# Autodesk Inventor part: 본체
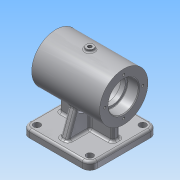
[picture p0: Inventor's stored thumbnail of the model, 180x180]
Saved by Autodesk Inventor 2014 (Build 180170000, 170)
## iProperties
Created: 2019-06
Part Number: 본체
Material: 알루미늄 6061
Document SubType Name: Modeling
Designer: user
Density: 2.71 g/cm^3
Appearance: 알루미늄 - 평지
Mass: 688.176 g
Surface Area: 608.027 cm^2
Volume: 253.94 cm^3
Author: user
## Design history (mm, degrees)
sketch "스케치1"
  geometry: L1 (-45, 0)-(45, 0); L2 (-45, 0)-(-45, 32); L3 (-45, 32)-(45, 32); L4 (45, 32)-(45, 0); L5 (-45, 20)-(-30, 20); L6 (-30, 20)-(-30, 17); L7 (-30, 17)-(-24, 17); L8 (-24, 17)-(-24, 25); L9 (-24, 25)-(24, 25); L10 (24, 25)-(24, 17); L11 (24, 17)-(30, 17); L12 (30, 17)-(30, 20); L13 (30, 20)-(45, 20); 2 further points
  constraints: 26 end point, 7 parallel, 4 perpendicular, 2 point on line, 1 coincident, 1 collinear, 1 horizontal, 1 midpoint
  dimensions: "d0" = 90 distance of L1.end L1.start; "d1" = 64 diameter of L3 L1; "d2" = 34 diameter of L7 L1; "d3" = 40 diameter of L5 L1; "d4" = 34 diameter of L11 L1; "d5" = 40 diameter of L13 L1; "d6" = 50 diameter of L9 L1; "d7" = 48 distance between parallel lines of L10 L8; "d8" = 15 distance between parallel lines of L6 L2; "d9" = 15 distance between parallel lines of L4 L12; "d10" = 6 distance between parallel lines of L8 L6; "d11" = 6 distance between parallel lines of L12 L10 (derived)
revolve "회전1" sketch "스케치1" stored, may be unused: angle "d12" = 90 deg
sketch "스케치2"
  geometry: L1 (-45, -55)-(45, -55); L2 (45, -55)-(45, -65); L3 (45, -65)-(-45, -65); L4 (-45, -65)-(-45, -55); 2 further points
  constraints: 8 end point, 2 parallel, 1 horizontal, 1 midpoint, 1 perpendicular, 1 vertical alignment
  dimensions: "d13" = 10 distance between parallel lines of L1 L3; "d14" = 90 distance between parallel lines of L2 L4; "d15" = 65 distance from line of L3 point (0, 0)
extrude "돌출1" join sketch "스케치2" stored distance "d16" = 90; taper "d17" = 0 deg
sketch "스케치3"
  geometry: L1 (40, -40)-(50, -40); L2 (50, -40)-(50, -50); L3 (50, -50)-(40, -50); L4 (40, -50)-(40, -40); L5 (40, -40)-(50, -50); L6 (50, -40)-(40, -50); 1 further point
  constraints: 12 end point, 2 midpoint, 2 parallel, 1 horizontal, 1 perpendicular
  dimensions: "d18" = 10 distance of L2.end L3.end; "d19" = 10 distance of L1.end L2.end
extrude "돌출2" join sketch "스케치3" stored distance "d20" = 90; taper "d21" = 0 deg
sketch "스케치4"
  geometry: L1 (24, 25)-(-24, 25) reference; L2 (-24, 25)-(-24, 17) reference; L3 (-24, 17)-(-30, 17) reference; L4 (-30, 17)-(-30, 20) reference; L5 (-30, 20)-(-45, 20) reference; L6 (-45, 20)-(-45, 32) reference; L7 (-45, 32)-(45, 32) reference; L8 (45, 32)-(45, 20) reference; L9 (45, 20)-(30, 20) reference; L10 (30, 20)-(30, 17) reference; L11 (30, 17)-(24, 17) reference; L12 (24, 17)-(24, 25) reference; L13 (-24, -25)-(24, -25) reference; L14 (24, -25)-(24, -17) reference; L15 (24, -17)-(30, -17) reference; L16 (30, -17)-(30, -20) reference; L17 (30, -20)-(45, -20) reference; L18 (45, -20)-(45, -32) reference; L19 (45, -32)-(5, -32) reference; L20 (5, -32)-(5, -55) reference; L21 (5, -55)-(45, -55) reference; L22 (45, -55)-(45, -65) reference; L23 (45, -65)-(-45, -65) reference; L24 (-45, -65)-(-45, -55) reference; L25 (-45, -55)-(-5, -55) reference; L26 (-5, -55)-(-5, -32) reference; L27 (-5, -32)-(-45, -32) reference; L28 (-45, -32)-(-45, -20) reference; L29 (-45, -20)-(-30, -20) reference; L30 (-30, -20)-(-30, -17) reference; L31 (-30, -17)-(-24, -17) reference; L32 (-24, -17)-(-24, -25) reference; L33 (-35, -32)-(-35, -55); L34 (35, -32)-(35, -55); 1 further point
  constraints: 4 end point, 4 point on line, 2 parallel
  dimensions: "d22" = 35 distance from line of L33 point (0, 0); "d23" = 35 distance from line of L34 point (0, 0)
feature "리브1" sketch "스케치4" dims "d24" = 1, "d25" = 10, "d26" = 0, "d27" = 0, "d28" = 1, "d29" = 1
sketch "스케치5"
  geometry: L1 (-45, -55)-(-5, -55) reference; L2 (-5, -55)-(-5, -31.607) reference; L3 (5, -31.607)-(5, -55) reference; L4 (5, -55)-(45, -55) reference; L5 (45, -55)-(45, -65) reference; L6 (45, -65)-(-45, -65) reference; L7 (-45, -65)-(-45, -55) reference; L8 (-23.058, -22.189)-(-35, -55); L9 (23.058, -22.189)-(35, -55); C1 r 25 at (0, 0) reference; A1 r 32 centre (0, 0) between (5, -31.607) and (-5, -31.607) reference; 1 further point
  constraints: 4 end point, 2 point on circle, 2 point on line
  dimensions: "d30" = 10 distance from line of L7 L8.end; "d31" = 10 distance from line of L5 L9.end; "d32" = 110 deg angle of L1 L8; "d33" = 110 deg angle of L4 L9
feature "리브2" sketch "스케치5" dims "d34" = 1, "d35" = 10, "d36" = 0, "d37" = 0, "d38" = 1, "d39" = 1
fillet "모깎기1" dims "d40" = 10
sketch "스케치6"
  geometry: L1 (-5, -5)-(75, -85); L2 (75, -5)-(-5, -85); C1 r 4.5 at (0, -10); C2 r 4.5 at (0, -80); C3 r 4.5 at (70, -10); C4 r 4.5 at (70, -80); A1 r 10 centre (70, -80) between (70, -90) and (80, -80) reference; A2 r 10 centre (70, -10) between (80, -10) and (70, 0) reference; A3 r 10 centre (0, -10) between (0, 0) and (-10, -10) reference; A4 r 10 centre (0, -80) between (-10, -80) and (0, -90) reference; 1 further point
  constraints: 4 centre point, 4 coincident, 4 end point, 2 midpoint
  dimensions: "d42" = 9 diameter of C1; "d43" = 9 diameter of C2; "d44" = 9 diameter of C3; "d45" = 9 diameter of C4
extrude "돌출3" cut sketch "스케치6" stored distance "d52" = 90; taper "d53" = 0 deg
chamfer "모따기1" distance "d61" = 1; stored, may be unused: second distance "d62" = 2, angle "d63" = 45 deg
fillet "모깎기2" dims "d64" = 3
fillet "모깎기3" dims "d65" = 0.6
node "작업 평면1"
sketch "스케치9"
  geometry: C1 r 5 at (0, 0); 1 further point
  constraints: 1 centre point, 1 coincident
  dimensions: "d67" = 10 diameter of C1
extrude "돌출4" join sketch "스케치9" stored distance "d68" = 5; taper "d69" = 0 deg
sketch "스케치10"
  geometry: C1 r 5 at (0, 0) reference; 1 further point
  constraints: 1 coincident
hole "구멍1" sketch "스케치10" at (0, 0) diameter "d70" = 4.917; stored, may be unused: countersink angle "d74" = 90 deg, drill point angle "d76" = 118 deg; dims "d71" = 6, "d72" = 4, "d73" = 2, "d75" = 8
fillet "모깎기4" dims "d77" = 3
fillet "모깎기5" dims "d78" = 3
fillet "모깎기6" dims "d79" = 3
fillet "모깎기7" dims "d80" = 3
sketch "스케치11"
  geometry: L1 (0, 0)-(25, 0); C1 r 21 at (0, 0) reference; 1 further point
  constraints: 2 end point, 1 coincident, 1 horizontal
  dimensions: "d81" = 25 distance of L1.start L1.end
hole "구멍2" sketch "스케치11" at (25, 0) diameter "d82" = 3.242; stored, may be unused: countersink angle "d86" = 90 deg, drill point angle "d88" = 118 deg; dims "d83" = 7, "d84" = 4, "d85" = 2, "d87" = 9
sketch "스케치12"
  geometry: L1 (35, 65)-(-35, 65) reference; L2 (45, 58)-(45, 65) reference; 2 further points
  constraints: 1 other
  dimensions: "d92" = 45 distance from line of L2 point (0, 61); "d93" = 4 distance from line of point (0, 61) L1
feature "엠보싱1" sketch "스케치12" dims "d13" = 10, "d14" = 90, "d15" = 65, "d94" = 0.5, "d95" = 0
fillet "모깎기8" dims "d96" = 2
node "솔리드1"
mirror "대칭1"
mirror "대칭2"
pattern_circular "원형 패턴1" dims angle "d90" = 360 deg
mirror "대칭3"
node "절단 모서리 투영1"
node "절단 모서리 투영2"
other parameters: "d66" = 35
